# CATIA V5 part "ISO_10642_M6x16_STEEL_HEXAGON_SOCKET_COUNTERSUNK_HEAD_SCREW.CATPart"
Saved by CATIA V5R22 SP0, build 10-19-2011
Part number: ISO 10642 SCREW M6x16 STEEL HEXAGON SOCKET COUNTERSUNK HEAD
Publications: "Mating Edge", "Axis"
Bounding box of the stored display mesh (mm): x -16.35 to 0, y -6.719 to 6.719, z -6.714 to 6.714
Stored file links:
  D:\PER\CAO_PER_MODIF_2025\CAO_PER_pick&place_2024P\ISO_10642_M6x16_STEEL_HEXAGON_SOCKET_COUNTERSUNK_HEAD_SCREW.CATPart
  C:\Program Files\Dassault Systemes\B22\win_b64\startup\components\MechanicalStandardParts\EN_Standards\Design_Tables\EN_ISO_10642_HEXAGON_SOCKET_COUNTERSUNK_SCREW.txt
  C:\Program Files\Dassault Systemes\B22\win_b64\startup\components\MechanicalStandardParts\ISO_Standards\Design_Tables\ISO_10642_HEXAGON_SOCKET_COUNTERSUNK_SCREW.txt
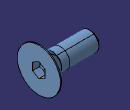
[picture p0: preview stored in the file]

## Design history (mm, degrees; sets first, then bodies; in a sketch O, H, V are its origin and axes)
Parameters
  l_length_nom = 16 mm
  b_ref = 24
  l_length_min = 15.65 mm
  l_length_max = 16.35 mm
  dk_head_dia_max = 13.44 mm
  dk_head_dia_min = 11.34 mm
  ls = 6.72 mm
  k_hed_depth = 3.72 mm
  r = 0.25 mm
  s_across_flats = 4 mm
  t_insert_depth = 2.2 mm
  d_dia = 6 mm
  threading = 9.28 mm
  p_pitch = 1 mm
Body1 "PartBody" (main body)
  Sketch1 on zx-plane, origin (0, 0, 0), H (-1, 0, 0), V (0, 0, 1)
    line L1 (0, 6.72) -> (0.3333, 6.72)
    point P2 (0.3333, 6.72)
    line L2 (0.3333, 6.72) -> (4.0533, 3)
    line L3 (4.0533, 3) -> (6.72, 3)
    line L4 (6.72, 3) -> (6.72, 2.9268)
    point P5 (6.72, 2.9268)
    line L5 (6.72, 2.9268) -> (15.8087, 2.9268)
    point P6 (15.8087, 2.9268)
    line L6 (15.8087, 2.9268) -> (16.35, 2.3855)
    axis line L7 (-30, 0) -> (125, 0)
    line L8 (16.35, 2.3855) -> (16.35, 0)
    point P10 (16.35, 0)
    line L9 (0, 6.72) -> (0, 0)
    distance L9 P5 = 6.72 {= ls}
    distance L9 L8 = 16.35 {= l_length_max}
    angle L5 L6 = 45
    distance L5 L7 = 2.9268 {= d_dia /2.05}
    distance L3 L7 = 3 {= d_dia  /2}
    angle L7 L2 = 45
    distance L1 L7 = 6.72 {= dk_head_dia_max /2}
    distance L9 P2 = 0.3333 {= p_pitch /3}
    distance P6 L8 = 0.5413 {= p_pitch *0.5413}
    horizontal: L1 H, L3 H, L5 H, L7 H
    vertical: L4 V, L9 V
    fix: L7
    coincidence: P10 L7
  Shaft1: profile Sketch1, axis Sketch1.L7, angle 360
  Body2
    Sketch2 on face of Shaft1, origin (0, 0, 0), H (0, 1, 0), V (0, 0, 1)
      point P1 (2, -1.1547)
      point P2 (2, 1.1547)
      point P3 (0, 2.3094)
      point P4 (-2, 1.1547)
      point P5 (-2, -1.1547)
      point P6 (0, -2.3094)
      point P7 (2, 0)
      line L1 (2, -1.1547) -> (2, 1.1547)
      line L2 (2, 1.1547) -> (0, 2.3094)
      line L3 (0, 2.3094) -> (-2, 1.1547)
      line L4 (-2, 1.1547) -> (-2, -1.1547)
      line L5 (-2, -1.1547) -> (0, -2.3094)
      line L6 (0, -2.3094) -> (2, -1.1547)
      construction line L7 (0, 0) -> (2, 0)
      construction circle A1 centre (0, 0) radius 2.3094
      construction arc A2 centre (-2, -1.1547) radius 2.3094 from (-2, 1.1547) to (0, -2.3094) cw
      construction arc A3 centre (2, 1.1547) radius 2.3094 from (0, 2.3094) to (2, -1.1547) ccw
      point P8 (-2, -1.1547)
      point P9 (2, 1.1547)
      distance L1 L4 = 4 {= s_across_flats}
      horizontal: L7 H
      coincidence: A1 P1, A1 P2, A1 P3, A1 P4, A1 P5, A1 P6, A2 P4, A2 P6, A2 O, P8 P5, A3 P3, A3 P1, A3 O, P9 P2
      midpoint: P7 L1
    Pad1: profile Sketch2, direction (-1, 0, 0), length 20
    Body3
      Sketch3 on zx-plane, origin (0, 0, 0), H (-1, 0, 0), V (0, 0, 1)
        line L1 (0, 0) -> (0, 2.3094)
        line L2 (0, 2.3094) -> (2.2, 2.3094)
        point P2 (2.2, 2.3094)
        line L3 (2.2, 2.3094) -> (3.5333, 0)
        point P3 (3.5333, 0)
        axis line L4 (-13.9938, 0) -> (46.4324, 0)
        reference projected line E1 (0, 2.3094) -> (20, 2.3094) from edge [face of Pad1 | face of Pad1]
        angle L3 L4 = 60
        distance L1 P2 = 2.2 {= t_insert_depth}
        vertical: L1 V
        horizontal: L2 H, L4 H
        fix: L4
        coincidence: L2 E1, P3 L4
      Shaft2: profile Sketch3, axis Sketch3.L4, angle 360
    Intersect1: tool Body3
  Remove1: tool Body2
  Fillet1: radius 0.25 {= r}, on edge [face of Shaft1 | face of Shaft1]
  Thread1: diameter 5.8537 {= d_dia /1.025}, depth 9.28 {= threading}, pitch 1, on face of Shaft1, from face of Shaft1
